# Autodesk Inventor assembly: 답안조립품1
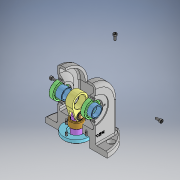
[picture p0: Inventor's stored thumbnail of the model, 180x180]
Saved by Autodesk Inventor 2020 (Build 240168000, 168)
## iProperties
Created: 2024-08
Part Number: 답안조립품1
Document SubType Name: Assembly
Designer: 1강의실14
Author: 1강의실14
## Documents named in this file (11)
- C:\Users\1강의실14\Desktop\740804V1011\답안조립품1.iam
- C:\Users\1강의실14\Desktop\740804V1011\본체.ipt
- C:\Users\1강의실14\Desktop\740804V1011\오일레스 부시 20 15.ipt
- C:\Users\1강의실14\Desktop\740804V1011\부시 커버.ipt
- C:\Users\1강의실14\Desktop\740804V1011\육각 소켓 머리 볼트 M4x10.ipt
- C:\Users\1강의실14\Desktop\740804V1011\링크.ipt
- C:\Users\1강의실14\Desktop\740804V1011\펀치.ipt
- C:\Users\1강의실14\Desktop\740804V1011\핀.ipt
- C:\Users\1강의실14\Desktop\740804V1011\E형 멈춤링 10-8.ipt
- C:\Users\1강의실14\Desktop\740804V1011\깊은 홈 볼 베어링 6904.ipt
- C:\Users\1강의실14\Desktop\740804V1011\칼라.ipt
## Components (2 placed, 2 different names)
1. 핀:1
2. E형 멈춤링 10-8:4
